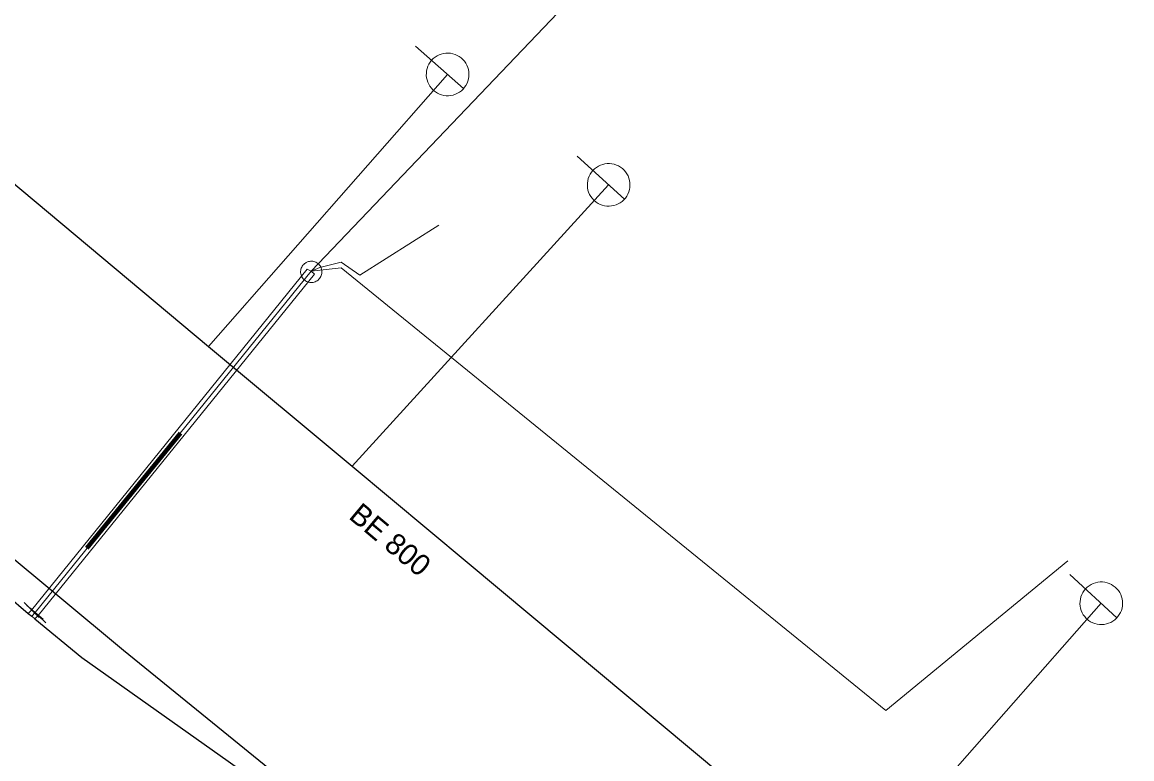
# Model space of a CAD drawing. Extents: x -807203 to -805207, y -993656 to -992505.
# Drawn here: x -806253.1 to -806201.1, y -993079.6 to -993045.1 of the extents above; entities that cross this region are included whole.
import ezdxf

# ---------------------------------------------------------------- set-up
doc = ezdxf.new("R2010")
doc.units = 0
doc.header["$LTSCALE"] = 0.4
for name, color, linetype, lineweight in [('1', 7, 'Continuous', 13), ('11', 7, 'Continuous', 13), ('13', 7, 'Continuous', 13), ('14', 7, 'Continuous', 25), ('17', 7, 'Continuous', 25), ('22', 7, 'Continuous', 13), ('23', 7, 'Continuous', 13), ('3', 7, 'Continuous', 106), ('34', 7, 'Continuous', 13)]:
    doc.layers.add(name, color=color, linetype=linetype, lineweight=lineweight)

msp = doc.modelspace()

# ---------------------------------------------------------------- linework, layer by layer
at = {"layer": '11'}
for p, q in [((-806233.195, -993047.535), (-806244.407, -993060.288)), ((-806225.644, -993052.713), (-806237.672, -993065.911)), ((-806202.545, -993072.334), (-806214.182, -993085.525))]:
    msp.add_line(p, q, dxfattribs=at)
at = {"layer": '13'}
for p, q in [((-806239.592, -993056.761), (-806218.881, -993035.058)), ((-806252.539, -993072.76), (-806239.592, -993056.761))]:
    msp.add_line(p, q, dxfattribs=at)
for points in [[(-806239.592, -993056.761), (-806239.185, -993056.585), (-806238.179, -993056.345), (-806237.317, -993056.952), (-806233.611, -993054.604)], [(-806252.699, -993072.649), (-806239.774, -993056.66), (-806239.592, -993056.761)], [(-806252.39, -993072.91), (-806239.43, -993056.896), (-806239.592, -993056.761)], [(-806239.592, -993056.761), (-806238.179, -993056.601), (-806212.643, -993077.356), (-806204.115, -993070.346)]]:
    msp.add_lwpolyline(points, dxfattribs=at)
at = {"layer": '14', "lineweight": 13}
for p, q in [((-806252.861, -993072.806), (-806252.699, -993072.649)), ((-806252.697, -993072.945), (-806252.539, -993072.76)), ((-806252.545, -993073.07), (-806252.39, -993072.91))]:
    msp.add_line(p, q, dxfattribs=at)
at = {"layer": '14'}
msp.add_lwpolyline([(-806254.43, -993051.92), (-806244.407, -993060.288), (-806237.672, -993065.911), (-806232.281, -993070.413), (-806214.182, -993085.525), (-806213.75, -993086.03)], dxfattribs=at)
at = {"layer": '17'}
for points in [[(-806264, -993062.975), (-806257.908, -993068.451), (-806254.907, -993071.059), (-806252.861, -993072.806), (-806252.697, -993072.945), (-806252.545, -993073.07), (-806250.353, -993074.879), (-806241.125, -993081.403), (-806232.688, -993088.282), (-806228.441, -993091.894), (-806220.09, -993098.618), (-806211.407, -993106.321), (-806206.008, -993110.745)], [(-806260.066, -993064.828), (-806248.392, -993074.528), (-806229.53, -993089.861), (-806208.251, -993107.276), (-806200.433, -993113.675), (-806198.425, -993115.318), (-806170.996, -993137.161), (-806169.414, -993138.403), (-806155.574, -993149.442), (-806086.497, -993204.202), (-806063.424, -993223.055)]]:
    msp.add_lwpolyline(points, dxfattribs=at)
at = {"layer": '22'}
for p, q in [((-806234.697, -993046.214), (-806232.444, -993048.194)), ((-806227.122, -993051.365), (-806224.905, -993053.386)), ((-806204.015, -993070.977), (-806201.81, -993073.011))]:
    msp.add_line(p, q, dxfattribs=at)
for points in [[(-806233.855, -993048.285), (-806233.769, -993048.353), (-806233.676, -993048.41), (-806233.577, -993048.458), (-806233.475, -993048.495), (-806233.367, -993048.52), (-806233.259, -993048.532), (-806233.149, -993048.533), (-806233.041, -993048.522), (-806232.933, -993048.499), (-806232.83, -993048.465), (-806232.73, -993048.42), (-806232.636, -993048.363), (-806232.549, -993048.297), (-806232.469, -993048.222), (-806232.398, -993048.138), (-806232.337, -993048.047), (-806232.285, -993047.95), (-806232.245, -993047.849), (-806232.217, -993047.743), (-806232.2, -993047.635), (-806232.195, -993047.525), (-806232.202, -993047.416), (-806232.221, -993047.308), (-806232.251, -993047.203), (-806232.293, -993047.102), (-806232.346, -993047.006), (-806232.409, -993046.916), (-806232.481, -993046.834), (-806232.562, -993046.76), (-806232.651, -993046.696), (-806232.745, -993046.641), (-806232.846, -993046.598), (-806232.95, -993046.565), (-806233.057, -993046.543), (-806233.167, -993046.535), (-806233.276, -993046.537), (-806233.385, -993046.552), (-806233.491, -993046.579), (-806233.593, -993046.617), (-806233.691, -993046.666), (-806233.783, -993046.725), (-806233.868, -993046.794), (-806233.945, -993046.873), (-806234.013, -993046.959), (-806234.07, -993047.052), (-806234.118, -993047.15), (-806234.155, -993047.254), (-806234.18, -993047.361), (-806234.192, -993047.469), (-806234.194, -993047.579), (-806234.183, -993047.688), (-806234.16, -993047.795), (-806234.127, -993047.899), (-806234.081, -993047.998), (-806234.025, -993048.092), (-806233.958, -993048.18), (-806233.883, -993048.259)], [(-806226.317, -993053.451), (-806226.233, -993053.52), (-806226.141, -993053.58), (-806226.042, -993053.629), (-806225.941, -993053.667), (-806225.834, -993053.694), (-806225.726, -993053.709), (-806225.616, -993053.712), (-806225.507, -993053.703), (-806225.399, -993053.682), (-806225.295, -993053.649), (-806225.195, -993053.606), (-806225.1, -993053.551), (-806225.011, -993053.486), (-806224.93, -993053.412), (-806224.858, -993053.33), (-806224.795, -993053.241), (-806224.742, -993053.145), (-806224.7, -993053.044), (-806224.67, -993052.938), (-806224.651, -993052.831), (-806224.644, -993052.721), (-806224.649, -993052.612), (-806224.666, -993052.503), (-806224.694, -993052.398), (-806224.734, -993052.296), (-806224.786, -993052.2), (-806224.847, -993052.108), (-806224.918, -993052.025), (-806224.998, -993051.95), (-806225.085, -993051.884), (-806225.178, -993051.827), (-806225.278, -993051.782), (-806225.381, -993051.747), (-806225.489, -993051.724), (-806225.598, -993051.713), (-806225.707, -993051.714), (-806225.816, -993051.727), (-806225.923, -993051.752), (-806226.026, -993051.788), (-806226.125, -993051.835), (-806226.218, -993051.893), (-806226.304, -993051.961), (-806226.382, -993052.038), (-806226.451, -993052.122), (-806226.511, -993052.214), (-806226.56, -993052.312), (-806226.598, -993052.415), (-806226.625, -993052.521), (-806226.64, -993052.63), (-806226.644, -993052.739), (-806226.635, -993052.848), (-806226.614, -993052.955), (-806226.582, -993053.06), (-806226.538, -993053.16), (-806226.484, -993053.255), (-806226.419, -993053.344), (-806226.345, -993053.425)], [(-806203.223, -993073.068), (-806203.139, -993073.138), (-806203.047, -993073.198), (-806202.949, -993073.247), (-806202.848, -993073.287), (-806202.741, -993073.314), (-806202.633, -993073.33), (-806202.523, -993073.333), (-806202.415, -993073.324), (-806202.306, -993073.304), (-806202.202, -993073.273), (-806202.101, -993073.23), (-806202.006, -993073.175), (-806201.917, -993073.111), (-806201.836, -993073.038), (-806201.763, -993072.956), (-806201.7, -993072.867), (-806201.646, -993072.771), (-806201.603, -993072.67), (-806201.572, -993072.565), (-806201.553, -993072.458), (-806201.545, -993072.348), (-806201.549, -993072.239), (-806201.566, -993072.13), (-806201.593, -993072.025), (-806201.633, -993071.923), (-806201.683, -993071.826), (-806201.744, -993071.734), (-806201.814, -993071.651), (-806201.894, -993071.575), (-806201.981, -993071.508), (-806202.074, -993071.451), (-806202.173, -993071.405), (-806202.276, -993071.37), (-806202.383, -993071.346), (-806202.493, -993071.335), (-806202.602, -993071.335), (-806202.711, -993071.347), (-806202.818, -993071.371), (-806202.921, -993071.406), (-806203.02, -993071.453), (-806203.114, -993071.51), (-806203.2, -993071.577), (-806203.279, -993071.654), (-806203.349, -993071.738), (-806203.409, -993071.83), (-806203.458, -993071.927), (-806203.498, -993072.03), (-806203.525, -993072.136), (-806203.541, -993072.244), (-806203.545, -993072.353), (-806203.537, -993072.463), (-806203.516, -993072.57), (-806203.485, -993072.675), (-806203.441, -993072.775), (-806203.388, -993072.871), (-806203.324, -993072.96), (-806203.25, -993073.042)]]:
    msp.add_lwpolyline(points, close=True, dxfattribs=at)
at = {"layer": '23'}
for points in [[(-806239.278, -993056.401), (-806239.321, -993056.37), (-806239.367, -993056.344), (-806239.415, -993056.325), (-806239.465, -993056.309), (-806239.515, -993056.298), (-806239.568, -993056.294), (-806239.62, -993056.295), (-806239.672, -993056.301), (-806239.723, -993056.312), (-806239.772, -993056.328), (-806239.821, -993056.35), (-806239.866, -993056.377), (-806239.908, -993056.408), (-806239.945, -993056.443), (-806239.98, -993056.482), (-806240.011, -993056.526), (-806240.036, -993056.57), (-806240.057, -993056.62), (-806240.073, -993056.668), (-806240.084, -993056.72), (-806240.088, -993056.773), (-806240.087, -993056.825), (-806240.081, -993056.878), (-806240.07, -993056.929), (-806240.053, -993056.977), (-806240.03, -993057.025), (-806240.004, -993057.07), (-806239.973, -993057.112), (-806239.937, -993057.15), (-806239.898, -993057.185), (-806239.856, -993057.215), (-806239.81, -993057.241), (-806239.762, -993057.262), (-806239.712, -993057.278), (-806239.662, -993057.287), (-806239.609, -993057.292), (-806239.556, -993057.292), (-806239.504, -993057.286), (-806239.453, -993057.274)], [(-806240.057, -993056.62), (-806240.073, -993056.668), (-806240.084, -993056.72), (-806240.088, -993056.773), (-806240.087, -993056.825), (-806240.081, -993056.878), (-806240.07, -993056.929), (-806240.053, -993056.977), (-806240.03, -993057.025), (-806240.004, -993057.07), (-806239.973, -993057.112), (-806239.937, -993057.15), (-806239.898, -993057.185), (-806239.856, -993057.215), (-806239.81, -993057.241), (-806239.762, -993057.262), (-806239.712, -993057.278), (-806239.662, -993057.287), (-806239.609, -993057.292), (-806239.556, -993057.292), (-806239.504, -993057.286), (-806239.453, -993057.274), (-806239.404, -993057.258), (-806239.356, -993057.235), (-806239.311, -993057.21), (-806239.269, -993057.177), (-806239.232, -993057.142), (-806239.197, -993057.103), (-806239.167, -993057.06), (-806239.141, -993057.015), (-806239.119, -993056.966), (-806239.105, -993056.916), (-806239.094, -993056.865), (-806239.089, -993056.814), (-806239.091, -993056.761), (-806239.095, -993056.709), (-806239.107, -993056.659), (-806239.124, -993056.608), (-806239.146, -993056.56), (-806239.173, -993056.515)], [(-806239.453, -993057.274), (-806239.404, -993057.258), (-806239.356, -993057.235), (-806239.311, -993057.21), (-806239.269, -993057.177), (-806239.232, -993057.142), (-806239.197, -993057.103), (-806239.167, -993057.06), (-806239.141, -993057.015), (-806239.119, -993056.966), (-806239.105, -993056.916), (-806239.094, -993056.865), (-806239.089, -993056.814), (-806239.091, -993056.761), (-806239.095, -993056.709), (-806239.107, -993056.659), (-806239.124, -993056.608), (-806239.146, -993056.56), (-806239.173, -993056.515), (-806239.205, -993056.474), (-806239.239, -993056.436), (-806239.278, -993056.401), (-806239.321, -993056.37), (-806239.367, -993056.344), (-806239.415, -993056.325), (-806239.465, -993056.309), (-806239.515, -993056.298), (-806239.568, -993056.294), (-806239.62, -993056.295), (-806239.672, -993056.301), (-806239.723, -993056.312), (-806239.772, -993056.328), (-806239.821, -993056.35), (-806239.866, -993056.377), (-806239.908, -993056.408), (-806239.945, -993056.443), (-806239.98, -993056.482), (-806240.011, -993056.526), (-806240.036, -993056.57), (-806240.057, -993056.62)], [(-806239.173, -993056.515), (-806239.205, -993056.474), (-806239.239, -993056.436), (-806239.278, -993056.401)]]:
    msp.add_lwpolyline(points, dxfattribs=at)
at = {"layer": '3'}
msp.add_line((-806250.114, -993069.754), (-806245.721, -993064.356), dxfattribs=at)
at = {"layer": '3', "lineweight": 100}
msp.add_line((-806250.114, -993069.754), (-806245.721, -993064.356), dxfattribs=at)
at = {"layer": '34'}
for p, q in [((-806253.047, -993072.29), (-806252.351, -993073.008)), ((-806252.92, -993072.436), (-806252.158, -993073.084)), ((-806252.75, -993072.563), (-806252.03, -993073.257))]:
    msp.add_line(p, q, dxfattribs=at)

# ---------------------------------------------------------------- texts
at = {"layer": '1'}
msp.add_text('BE 800', height=1, rotation=320, dxfattribs=at).set_placement((-806237.881, -993068.323))

doc.saveas('drawing.dxf')
